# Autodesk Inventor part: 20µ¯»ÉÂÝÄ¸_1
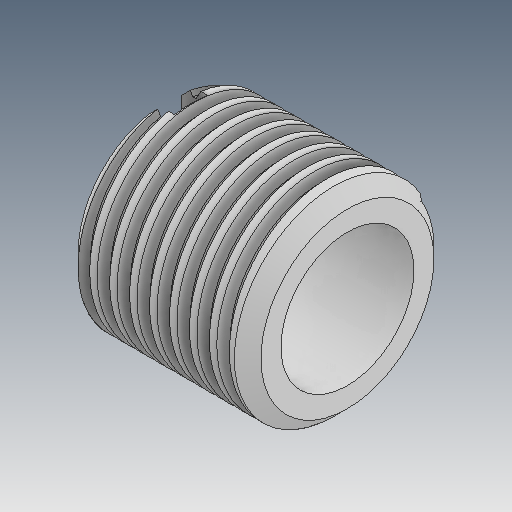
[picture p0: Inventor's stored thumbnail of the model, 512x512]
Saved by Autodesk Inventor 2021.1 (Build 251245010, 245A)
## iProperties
Created: 2019-12
Part Number: 20µ¯»ÉÂÝÄ¸_1
Material: Ogólny
Document SubType Name: Modeling
Designer: user
Density: 1 g/cm^3
Appearance: Domyślna
Author: user
Revision Number: ÈÎºÎ
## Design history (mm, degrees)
feature "ÊäÈë1"
node "Bryła1"
